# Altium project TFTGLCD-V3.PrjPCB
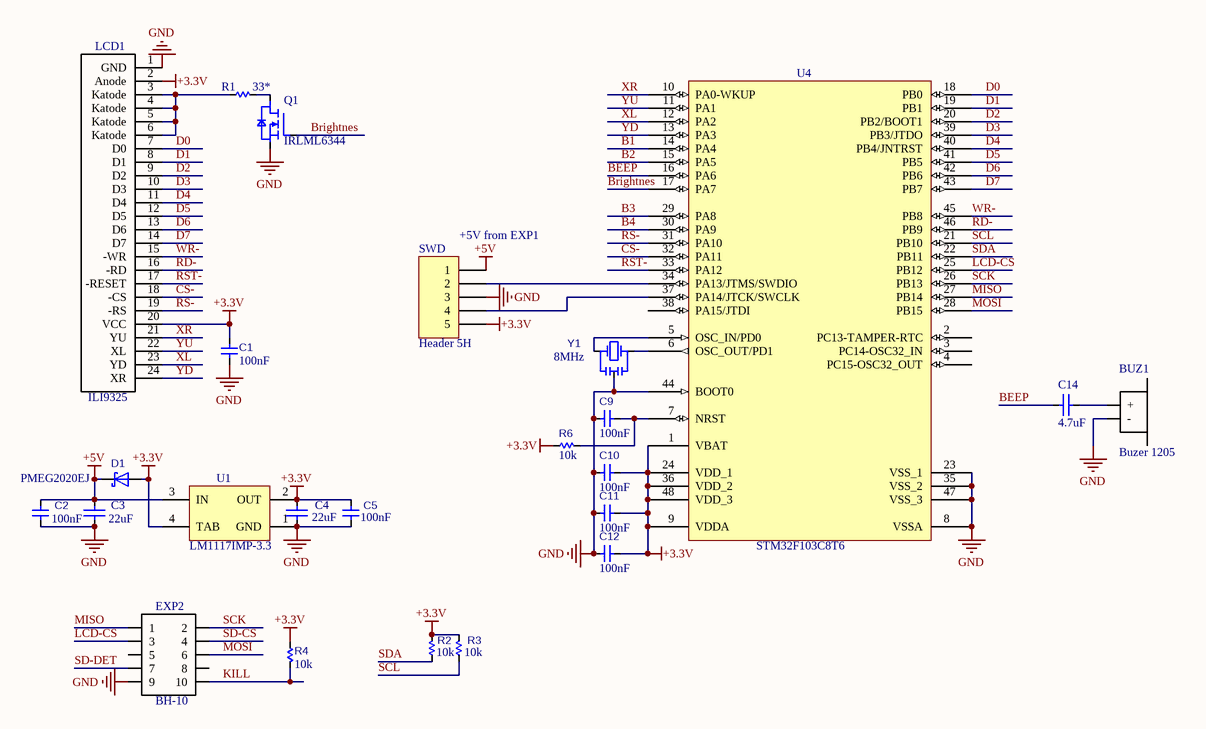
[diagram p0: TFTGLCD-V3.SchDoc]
1 sheet, 24 parts. Net scope: global (net labels, ports and power ports of the same name join across sheets).
Board file: TFTGLCD-V3.PcbDoc

## Sheet TFTGLCD-V3.SchDoc: TFTGLCD Panel V3
size A4; Engineer: Serj_K; Revision: 1.0; SheetNumber: 1; SheetTotal: 1

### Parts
BUZ1  Buzer 1205  [Buzer_12xx]
C1  value 100nF  [C0603_Samsung]  (hidden comment: Cap)
C2  value 100nF  [C0603_Samsung]  (hidden comment: Cap)
C3  value 22uF  [C1206_Murata]  (hidden comment: Cap)
C4  value 22uF  [C1206_Murata]  (hidden comment: Cap)
C5  value 100nF  [C0603_Samsung]  (hidden comment: Cap)
C9  value 100nF  [C0603_Samsung]  (hidden comment: Cap)
C10  value 100nF  [C0603_Samsung]  (hidden comment: Cap)
C11  value 100nF  [C0603_Samsung]  (hidden comment: Cap)
C12  value 100nF  [C0603_Samsung]  (hidden comment: Cap)
C14  value 4.7uF  [C1206_Murata]  (hidden comment: Cap)
D1  Part Label: PMEG2020EJ  [SOD323FL_NXP]  (hidden comment: D_Schottky)
EXP2  BH-10  [BH-10 Slot small]
LCD1  ILI9325  [Mini-IPhone 24pin]
Q1  IRLML6344  [SOT23-3_IR]
R1  value 33*  [R0805_UniOhm]  (hidden comment: R)
R2  value 10k  [R0603_UniOhm]  (hidden comment: R)
R3  value 10k  [R0603_UniOhm]  (hidden comment: R)
R4  value 10k  [R0603_UniOhm]  (hidden comment: R)
R6  value 10k  [R0603_UniOhm]  (hidden comment: R)
SWD  Header 5H  [HDR1X5H]
U1  LM1117IMP-3.3  [MP04A_N]
U4  STM32F103C8T6  [LQFP48_N]
Y1  value 8MHz  [CSTCE_G]  (hidden comment: XTAL_CAP)

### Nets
+3.3V: C1.2 C4.2 C5.2 C10.2 C11.2 C12.2 D1.A LCD1.2(Anode) LCD1.20(VCC) R2.2 R3.2 R4.1 R6.1 SWD.5 U1.2(OUT) U1.4(TAB) U4.1(VBAT) U4.9(VDDA) U4.24(VDD_1) U4.36(VDD_2) U4.48(VDD_3)
+5V: C2.2 C3.2 D1.C SWD.1 U1.3(IN)
GND: BUZ1.2(-) C1.1 C2.1 C3.1 C4.1 C5.1 C9.1 C10.1 C11.1 C12.1 EXP2.9 LCD1.1(GND) Q1.2(S) SWD.3 U1.1(GND) U4.8(VSSA) U4.23(VSS_1) U4.35(VSS_2) U4.44(BOOT0) U4.47(VSS_3) Y1.2(G)
B1: U4.14(PA4)
B2: U4.15(PA5)
B3: U4.29(PA8)
B4: U4.30(PA9)
BEEP: C14.2 U4.16(PA6)
Brightnes: Q1.1(G) U4.17(PA7)
CS-: LCD1.18(-CS) U4.32(PA11)
D0: LCD1.7(D0) U4.18(PB0)
D1: LCD1.8(D1) U4.19(PB1)
D2: LCD1.9(D2) U4.20(PB2/BOOT1)
D3: LCD1.10(D3) U4.39(PB3/JTDO)
D4: LCD1.11(D4) U4.40(PB4/JNTRST)
D5: LCD1.12(D5) U4.41(PB5)
D6: LCD1.13(D6) U4.42(PB6)
D7: LCD1.14(D7) U4.43(PB7)
KILL: EXP2.10 R4.2
LCD-CS: EXP2.3 U4.25(PB12)
MISO: EXP2.1 U4.27(PB14)
MOSI: EXP2.6 U4.28(PB15)
RD-: LCD1.16(-RD) U4.46(PB9)
RS-: LCD1.19(-RS) U4.31(PA10)
RST-: LCD1.17(-RESET) U4.33(PA12)
SCK: EXP2.2 U4.26(PB13)
SCL: R3.1 U4.21(PB10)
SD-CS: EXP2.4
SD-DET: EXP2.7
SDA: R2.1 U4.22(PB11)
WR-: LCD1.15(-WR) U4.45(PB8)
XL: LCD1.23(YD) U4.12(PA2)
XR: LCD1.21(YU) U4.10(PA0-WKUP)
YD: LCD1.24(XR) U4.13(PA3)
YU: LCD1.22(XL) U4.11(PA1)
NetBUZ1_1: BUZ1.1(+) C14.1
NetC9_2: C9.2 R6.2 U4.7(NRST)
NetLCD1_3: LCD1.3(Katode) LCD1.4(Katode) LCD1.5(Katode) LCD1.6(Katode) R1.1
NetQ1_3: Q1.3(D) R1.2
NetSWD_2: SWD.2 U4.34(PA13/JTMS/SWDIO)
NetSWD_4: SWD.4 U4.37(PA14/JTCK/SWCLK)
NetU4_5: U4.5(OSC_IN/PD0) Y1.1(OSC1)
NetU4_6: U4.6(OSC_OUT/PD1) Y1.3(OSC2)

Not connected (* = marked no-connect by the designer): EXP2 5 8; U4 2(PC13-TAMPER-RTC) 3(PC14-OSC32_IN) 4(PC15-OSC32_OUT) 38(PA15/JTDI)

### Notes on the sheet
- (near SWD) +5V from EXP1

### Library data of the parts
BUZ1 = Buzer
C1 C2 C5 C9-C12 = CL10B104KB8NNNC: PartName: CL10; Part Label: C0603 100nF 10% X7R 50V; Manufacturer: Samsung Electro-Mechanics; Voltage: 50V; Tolerance: 10 %; Device: C; ShortName: C0603
C3 C4 C14 = GRM31CR71H475KA12L: PartName: GRM31; Part Label: C1206 4.7uF 10% X7R 50V; Manufacturer: muRata; Voltage: 50V; Tolerance: 10 %; Device: C; ShortName: C1206
D1 = PMEG2020EJ,115: 20V, 2A very low VF MEGA Schottky barrier rectifiers; Manufacturer: NXP Semiconductors; ClassName_u: Schottky SMD; Device: D
EXP2 = BH-10 Slot
LCD1 = Mini-IPhone-24pin
Q1 = IRLML6344TRPBF: 30 V, 5.0 A, 0.029 Ohm Single N-Channel HEXFET Power MOSFET; Manufacturer: International Rectifier; Device: Q; ShortName: NMOS
R1 = 0805S8F4700T50: PartName: 0805S; Part Label: R0805 470 1% TC100 150V; Manufacturer: uniOhm; TempCo: 100 ppm; Tolerance: 1 %; ShortName: R0805
R2-R4 R6 = 0603SAF1002T50: PartName: 0603SA; Part Label: R0603 10k 1% TC100 50V; Manufacturer: uniOhm; TempCo: 100 ppm; Tolerance: 1 %; ShortName: R0603
SWD = Header 5H: Header, 5-Pin, Right Angle
U1 = LM1117IMP-3.3: 800mA Low-Dropout Linear Regulator; Manufacturer: National Semiconductor; CompType: LDO IC; PackageTopMarking: XYTT*N05B; PowerWise: N
U4 = STM32F103C8T6: STM32 ARM-based 32-bit MCU with 64 Kbytes Flash, 48-pin LQFP, Industrial Temperature
Y1 = CSTCE10M0G55Z-R0: SMD 10 MHz 0.5%, 0.2%(TC) Build in Load Capacitance 33pF ± 20%; Manufacturer: muRata; ClassName_u: Ceramic Resonators SMD; Device: Y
